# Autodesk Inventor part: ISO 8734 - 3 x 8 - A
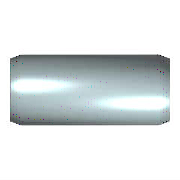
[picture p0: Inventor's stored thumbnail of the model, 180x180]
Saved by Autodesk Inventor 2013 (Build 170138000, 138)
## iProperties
Created: 2012-02
Part Number: ISO 8734 - 3 x 8 - A
Material: Stahl
Description: Zylinderstift
Document SubType Name: Modeling
Standard: ISO 8734
Designer: rYan
Standards Organization: DIN
Language: de-DE
Size Designation: 3 x 8 - A
Categories: <MemberInstance><Categories><Category DisplayName="Verbindungselemente" InternalName="e4da775c-781d-43d5-af7c-5136215cf5a6" Mnemonic="FSTN"><Category DisplayNam
Density: 7.85 g/cm^3
Mass: 0.439099 g
Surface Area: 0.870195 cm^2
Volume: 0.0559361 cm^3
IsCustomPart: 0
Author: rYan
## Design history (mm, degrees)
sketch "Skizze"
  geometry: C1 r 1.5 at (0, 0); 1 further point
  constraints: 1 centre point, 1 coincident
  dimensions: "d1" = 3 diameter of C1 (= NND)
extrude "Körper" new body sketch "Skizze" distance "d2" = 8 (= NLG); taper "d3" = 0 deg
body "Solid1"
chamfer "Fase1" distance "d4" = 0.5 (= PHH); stored, may be unused: angle "d5" = 15 deg (= FAWI), second distance "d11" = 0.5 (= PHH)
chamfer "Fase2" distance "d8" = 0.5 (= PHH); stored, may be unused: angle "d9" = 15 deg (= FAWI), second distance "d12" = 0.5 (= PHH)
other parameters: "NND" = 3 [user parameter; used in 1 equation term], "NLG" = 8 [user parameter; used in 1 equation term], "PHH" = 0.5 [user parameter; used in 5 equation terms], "FAWI" = 15 deg [user parameter; used in 2 equation terms], "d13" = 0, "d15" = 0, "d16" = 0, "PHH2" = 0.5 (= PHH) [user parameter], "FAWI2" = 15 deg [user parameter]
